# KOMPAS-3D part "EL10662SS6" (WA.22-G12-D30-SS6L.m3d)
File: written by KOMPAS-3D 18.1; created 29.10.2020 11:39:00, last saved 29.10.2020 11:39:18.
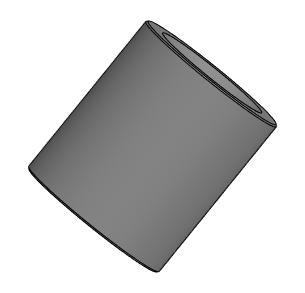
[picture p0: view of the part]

Document properties: Автор: user; Полное имя файла: Z:\20_Элхарт\БД\3D модели приборов для сайта\Переходники\EL10662SS6\EL10662SS6.m3d

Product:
- Part/product: EL10662SS6
    Масса: 0.114096

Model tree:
1. Операция без истории:1  (labels: EL10662SS6)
